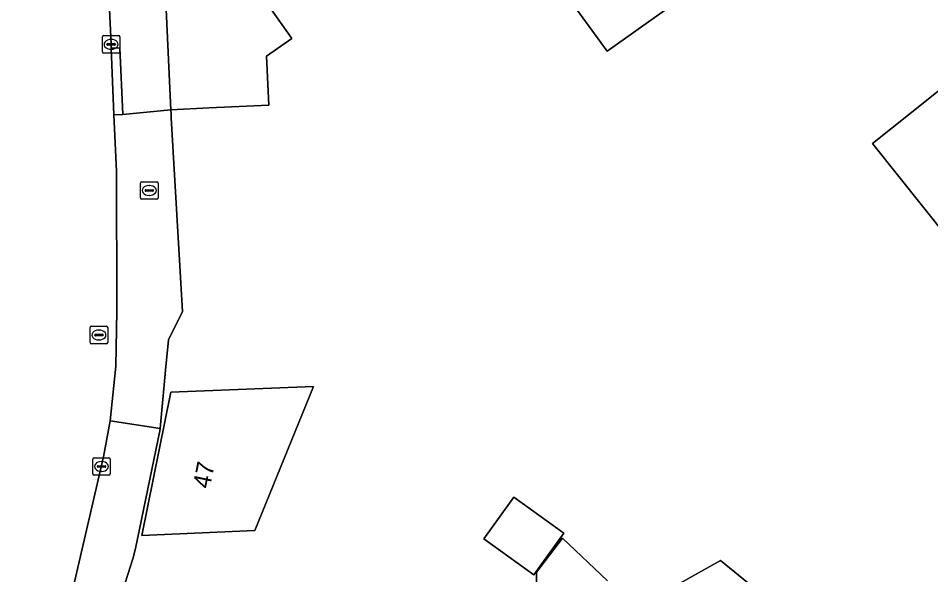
# Model space of a CAD drawing. Extents: x 159888 to 160761, y 384031 to 384750.
# Drawn here: x 160365.4 to 160417.5, y 384473.8 to 384505.5 of the extents above; entities that cross this region are included whole.
import ezdxf

# ---------------------------------------------------------------- set-up
doc = ezdxf.new("R2010")
doc.units = 0
for name, color, linetype in [('IMGEO_Brandkraan', 7, 'Continuous'), ('IMGEO_Erf', 7, 'Continuous'), ('IMGEO_Kolk', 7, 'Continuous'), ('IMGEO_Pand', 7, 'Continuous'), ('IMGEO_Pand_nummerreeks', 7, 'Continuous'), ('IMGEO_Rijbaan_lokaal_open', 7, 'Continuous'), ('IMGEO_Rioolput', 7, 'Continuous'), ('IMGEO_Voetpad_open', 7, 'Continuous')]:
    doc.layers.add(name, color=color, linetype=linetype)

msp = doc.modelspace()

# ---------------------------------------------------------------- linework, layer by layer
at = {"layer": 'IMGEO_Brandkraan'}
for p, q in [((160372.384, 384495.26), (160372.384, 384496.112)), ((160372.459, 384496.186), (160373.311, 384496.186)), ((160372.643, 384495.68), (160372.643, 384495.692)), ((160372.686, 384495.729), (160373.084, 384495.729)), ((160372.872, 384495.966), (160372.897, 384495.966)), ((160373.127, 384495.692), (160373.127, 384495.68)), ((160373.385, 384496.112), (160373.385, 384495.26)), ((160373.311, 384495.186), (160372.459, 384495.186)), ((160373.081, 384495.643), (160372.683, 384495.643)), ((160372.895, 384495.406), (160372.87, 384495.406))]:
    msp.add_line(p, q, dxfattribs=at)
for points in [[(160372.384, 384495.26), (160372.384, 384496.112)], [(160372.459, 384496.186), (160373.311, 384496.186)], [(160373.385, 384496.112), (160373.385, 384495.26)], [(160373.311, 384495.186), (160372.459, 384495.186)]]:
    msp.add_lwpolyline(points, dxfattribs=at)
for centre, radius, start, end in [((160372.461, 384496.11), 0.0765, 91.552, 178.448), ((160372.461, 384496.11), 0.0765, 91.552, 178.448), ((160372.683, 384495.689), 0.0403, 85.8775, 175.7526), ((160372.68, 384495.679), 0.0366, 178.938, 274.7102), ((160373.084, 384495.686), 0.043, 264.8664, 352.4533), ((160373.088, 384495.691), 0.0386, 1.7309, 96.639), ((160373.309, 384496.11), 0.0765, 1.552, 88.448), ((160373.309, 384496.11), 0.0765, 1.552, 88.448), ((160372.461, 384495.262), 0.0765, 181.552, 268.448), ((160372.461, 384495.262), 0.0765, 181.552, 268.448), ((160373.309, 384495.262), 0.0765, 271.552, 358.448), ((160373.309, 384495.262), 0.0765, 271.552, 358.448)]:
    msp.add_arc(centre, radius, start, end, dxfattribs=at)
for centre, major_axis, ratio, start_param, end_param in [((160372.871, 384495.686), (-0.387, 0.002), 0.722429, 4.712389, 7.853982), ((160372.896, 384495.686), (-0.39, 0.002), 0.717154, 1.570796, 4.712389)]:
    msp.add_ellipse(centre, major_axis=major_axis, ratio=ratio, start_param=start_param, end_param=end_param, dxfattribs=at)
at = {"layer": 'IMGEO_Erf'}
for points in [[(160414.971, 384514.963), (160399.007, 384503.642), (160391.34, 384514.142)], [(160379.819, 384506.057), (160381.01, 384504.358), (160379.581, 384503.355), (160379.704, 384500.554), (160376.3, 384500.397), (160374.106, 384500.295), (160374.123, 384500), (160374.133, 384499.834), (160374.788, 384488.773), (160373.98, 384487.169), (160373.814, 384485.44), (160373.502, 384482.102), (160373.49, 384481.978), (160372.091, 384475.256), (160371.947, 384474.664), (160371.667, 384473.77), (160370.165, 384469.09)], [(160425.564, 384484.062), (160414.155, 384498.367), (160416.215, 384500), (160420.926, 384503.774)], [(160394.977, 384472.426), (160394.977, 384473.913), (160396.464, 384475.846), (160399.032, 384473.413)], [(160401.316, 384472.23), (160405.49, 384474.582), (160407.845, 384472.647)]]:
    msp.add_lwpolyline(points, dxfattribs=at)
for points in [[(160372.453, 384475.995), (160374.111, 384484.184), (160382.264, 384484.507), (160378.9, 384476.283)], [(160394.831, 384473.764), (160391.977, 384475.816), (160393.679, 384478.184), (160396.533, 384476.132)]]:
    msp.add_lwpolyline(points, close=True, dxfattribs=at)
at = {"layer": 'IMGEO_Kolk'}
for p, q in [((160370.28, 384504.526), (160371.132, 384504.526)), ((160370.205, 384503.6), (160370.205, 384504.452)), ((160370.464, 384504.02), (160370.464, 384504.032)), ((160370.507, 384504.069), (160370.905, 384504.069)), ((160370.693, 384504.306), (160370.718, 384504.306)), ((160370.948, 384504.032), (160370.948, 384504.02)), ((160371.206, 384504.452), (160371.206, 384503.6)), ((160371.132, 384503.526), (160370.28, 384503.526)), ((160370.902, 384503.983), (160370.504, 384503.983)), ((160370.716, 384503.746), (160370.691, 384503.746)), ((160369.657, 384479.512), (160369.657, 384480.364)), ((160369.732, 384480.438), (160370.584, 384480.438)), ((160370.145, 384480.218), (160370.17, 384480.218)), ((160370.658, 384480.364), (160370.658, 384479.512)), ((160369.916, 384479.932), (160369.916, 384479.944)), ((160370.354, 384479.895), (160369.956, 384479.895)), ((160369.959, 384479.981), (160370.357, 384479.981)), ((160370.168, 384479.658), (160370.143, 384479.658)), ((160370.4, 384479.944), (160370.4, 384479.932)), ((160370.584, 384479.438), (160369.732, 384479.438))]:
    msp.add_line(p, q, dxfattribs=at)
for points in [[(160370.28, 384504.526), (160371.132, 384504.526)], [(160370.205, 384503.6), (160370.205, 384504.452)], [(160371.206, 384504.452), (160371.206, 384503.6)], [(160371.132, 384503.526), (160370.28, 384503.526)], [(160369.657, 384479.512), (160369.657, 384480.364)], [(160369.732, 384480.438), (160370.584, 384480.438)], [(160370.658, 384480.364), (160370.658, 384479.512)], [(160370.584, 384479.438), (160369.732, 384479.438)]]:
    msp.add_lwpolyline(points, dxfattribs=at)
for centre, radius, start, end in [((160370.282, 384504.45), 0.0765, 91.552, 178.448), ((160370.282, 384504.45), 0.0765, 91.552, 178.448), ((160371.13, 384504.45), 0.0765, 1.552, 88.448), ((160371.13, 384504.45), 0.0765, 1.552, 88.448), ((160370.504, 384504.029), 0.0403, 85.8775, 175.7526), ((160370.501, 384504.019), 0.0366, 178.938, 274.7102), ((160370.905, 384504.026), 0.043, 264.8664, 352.4533), ((160370.909, 384504.031), 0.0386, 1.7309, 96.639), ((160370.282, 384503.602), 0.0765, 181.552, 268.448), ((160370.282, 384503.602), 0.0765, 181.552, 268.448), ((160371.13, 384503.602), 0.0765, 271.552, 358.448), ((160371.13, 384503.602), 0.0765, 271.552, 358.448), ((160369.734, 384480.362), 0.0765, 91.552, 178.448), ((160369.734, 384480.362), 0.0765, 91.552, 178.448), ((160370.582, 384480.362), 0.0765, 1.552, 88.448), ((160370.582, 384480.362), 0.0765, 1.552, 88.448), ((160369.956, 384479.941), 0.0403, 85.8775, 175.7526), ((160369.953, 384479.931), 0.0366, 178.938, 274.7102), ((160370.357, 384479.938), 0.043, 264.8664, 352.4533), ((160370.361, 384479.943), 0.0386, 1.7309, 96.639), ((160369.734, 384479.514), 0.0765, 181.552, 268.448), ((160369.734, 384479.514), 0.0765, 181.552, 268.448), ((160370.582, 384479.514), 0.0765, 271.552, 358.448), ((160370.582, 384479.514), 0.0765, 271.552, 358.448)]:
    msp.add_arc(centre, radius, start, end, dxfattribs=at)
for centre, major_axis, ratio, start_param, end_param in [((160370.692, 384504.026), (-0.387, 0.002), 0.722429, 4.712389, 7.853982), ((160370.717, 384504.026), (-0.39, 0.002), 0.717154, 1.570796, 4.712389), ((160370.144, 384479.938), (-0.387, 0.002), 0.722429, 4.712389, 7.853982), ((160370.169, 384479.938), (-0.39, 0.002), 0.717154, 1.570796, 4.712389)]:
    msp.add_ellipse(centre, major_axis=major_axis, ratio=ratio, start_param=start_param, end_param=end_param, dxfattribs=at)
at = {"layer": 'IMGEO_Pand'}
for points in [[(160488.936, 384534.93), (160487.757, 384536.875), (160482.889, 384544.99), (160479.793, 384550.133), (160479.161, 384549.765), (160471.203, 384543.477), (160445.899, 384523.596), (160424.352, 384506.518), (160420.926, 384503.774), (160416.215, 384500), (160414.155, 384498.367), (160425.564, 384484.062), (160440.9, 384491.039), (160442.203, 384488.75), (160446.354, 384492.06), (160454.254, 384497.681), (160453.942, 384498.111), (160454.092, 384498.231), (160452.683, 384500), (160449.739, 384503.694)], [(160391.34, 384514.142), (160399.007, 384503.642), (160414.971, 384514.963), (160413.861, 384517.1), (160411.531, 384521.523), (160398.402, 384512.233), (160393.999, 384518.313), (160390.31, 384515.611)], [(160384.256, 384509.171), (160379.414, 384515.85), (160374.778, 384512.597), (160377.462, 384508.983), (160377.259, 384508.841), (160373.835, 384506.438), (160374.106, 384500.295), (160376.3, 384500.397), (160379.704, 384500.554), (160379.581, 384503.355), (160381.01, 384504.358), (160379.819, 384506.057)], [(160372.453, 384475.995), (160378.9, 384476.283), (160382.264, 384484.507), (160374.111, 384484.184)], [(160391.977, 384475.816), (160394.831, 384473.764), (160396.533, 384476.132), (160393.679, 384478.184)]]:
    msp.add_lwpolyline(points, close=True, dxfattribs=at)
at = {"layer": 'IMGEO_Rijbaan_lokaal_open'}
msp.add_lwpolyline([(160363.478, 384506.755), (160363.686, 384500), (160363.834, 384495.216), (160363.935, 384491.933), (160363.929, 384488.724), (160363.581, 384484.328), (160362.841, 384479.981), (160359.674, 384465.568), (160359.312, 384463.92), (160359.041, 384462.675), (160365.77, 384461.083), (160366.177, 384462.861), (160366.451, 384463.997), (160370.273, 384480.487), (160370.648, 384482.549), (160370.978, 384485.668), (160371.028, 384488.804), (160371.025, 384488.905), (160371.009, 384496.794), (160370.869, 384500), (160370.703, 384503.798), (160370.705, 384504.025), (160370.606, 384506.023)], dxfattribs=at)
at = {"layer": 'IMGEO_Rioolput'}
for p, q in [((160369.509, 384487.012), (160369.509, 384487.864)), ((160369.584, 384487.938), (160370.436, 384487.938)), ((160370.51, 384487.864), (160370.51, 384487.012)), ((160369.768, 384487.432), (160369.768, 384487.444)), ((160370.206, 384487.395), (160369.808, 384487.395)), ((160369.811, 384487.481), (160370.209, 384487.481)), ((160369.997, 384487.718), (160370.022, 384487.718)), ((160370.252, 384487.444), (160370.252, 384487.432)), ((160370.436, 384486.938), (160369.584, 384486.938)), ((160370.02, 384487.158), (160369.995, 384487.158))]:
    msp.add_line(p, q, dxfattribs=at)
for points in [[(160369.509, 384487.012), (160369.509, 384487.864)], [(160369.584, 384487.938), (160370.436, 384487.938)], [(160370.51, 384487.864), (160370.51, 384487.012)], [(160370.436, 384486.938), (160369.584, 384486.938)]]:
    msp.add_lwpolyline(points, dxfattribs=at)
for centre, radius, start, end in [((160369.586, 384487.862), 0.0765, 91.552, 178.448), ((160369.586, 384487.862), 0.0765, 91.552, 178.448), ((160370.434, 384487.862), 0.0765, 1.552, 88.448), ((160370.434, 384487.862), 0.0765, 1.552, 88.448), ((160369.808, 384487.441), 0.0403, 85.8775, 175.7526), ((160369.805, 384487.431), 0.0366, 178.938, 274.7102), ((160370.209, 384487.438), 0.043, 264.8664, 352.4533), ((160370.213, 384487.443), 0.0386, 1.7309, 96.639), ((160369.586, 384487.014), 0.0765, 181.552, 268.448), ((160369.586, 384487.014), 0.0765, 181.552, 268.448), ((160370.434, 384487.014), 0.0765, 271.552, 358.448), ((160370.434, 384487.014), 0.0765, 271.552, 358.448)]:
    msp.add_arc(centre, radius, start, end, dxfattribs=at)
for centre, major_axis, ratio, start_param, end_param in [((160369.996, 384487.438), (-0.387, 0.002), 0.722429, 4.712389, 7.853982), ((160370.021, 384487.438), (-0.39, 0.002), 0.717154, 1.570796, 4.712389)]:
    msp.add_ellipse(centre, major_axis=major_axis, ratio=ratio, start_param=start_param, end_param=end_param, dxfattribs=at)
at = {"layer": 'IMGEO_Voetpad_open'}
for points in [[(160369.699, 384526.823), (160369.721, 384525.722), (160369.741, 384524.723), (160370.051, 384517.498), (160370.606, 384506.023), (160370.705, 384504.025), (160370.703, 384503.798), (160371.202, 384503.819), (160371.368, 384500.026), (160374.106, 384500.295), (160373.835, 384506.438), (160373.239, 384516.529)], [(160399.032, 384473.413), (160396.464, 384475.846), (160394.977, 384473.913), (160394.977, 384472.426)], [(160407.845, 384472.647), (160405.49, 384474.582), (160401.316, 384472.23)]]:
    msp.add_lwpolyline(points, dxfattribs=at)
for points in [[(160370.869, 384500), (160371.368, 384500.026), (160371.202, 384503.819), (160370.703, 384503.798)], [(160371.009, 384496.794), (160371.025, 384488.905), (160371.028, 384488.804), (160370.978, 384485.668), (160370.648, 384482.549), (160373.502, 384482.102), (160373.814, 384485.44), (160373.98, 384487.169), (160374.788, 384488.773), (160374.133, 384499.834), (160374.123, 384500), (160374.106, 384500.295), (160371.368, 384500.026), (160370.869, 384500)], [(160371.667, 384473.77), (160371.947, 384474.664), (160372.091, 384475.256), (160373.49, 384481.978), (160373.502, 384482.102), (160370.648, 384482.549), (160370.273, 384480.487), (160366.451, 384463.997), (160366.177, 384462.861), (160365.77, 384461.083), (160365.728, 384460.934), (160368.454, 384460.332), (160370.226, 384468.109), (160370.165, 384469.09)]]:
    msp.add_lwpolyline(points, close=True, dxfattribs=at)

# ---------------------------------------------------------------- texts
at = {"layer": 'IMGEO_Pand_nummerreeks'}
msp.add_text('47', height=1, rotation=78.5583, dxfattribs=at).set_placement((160376.333, 384478.632))

doc.saveas('drawing.dxf')
